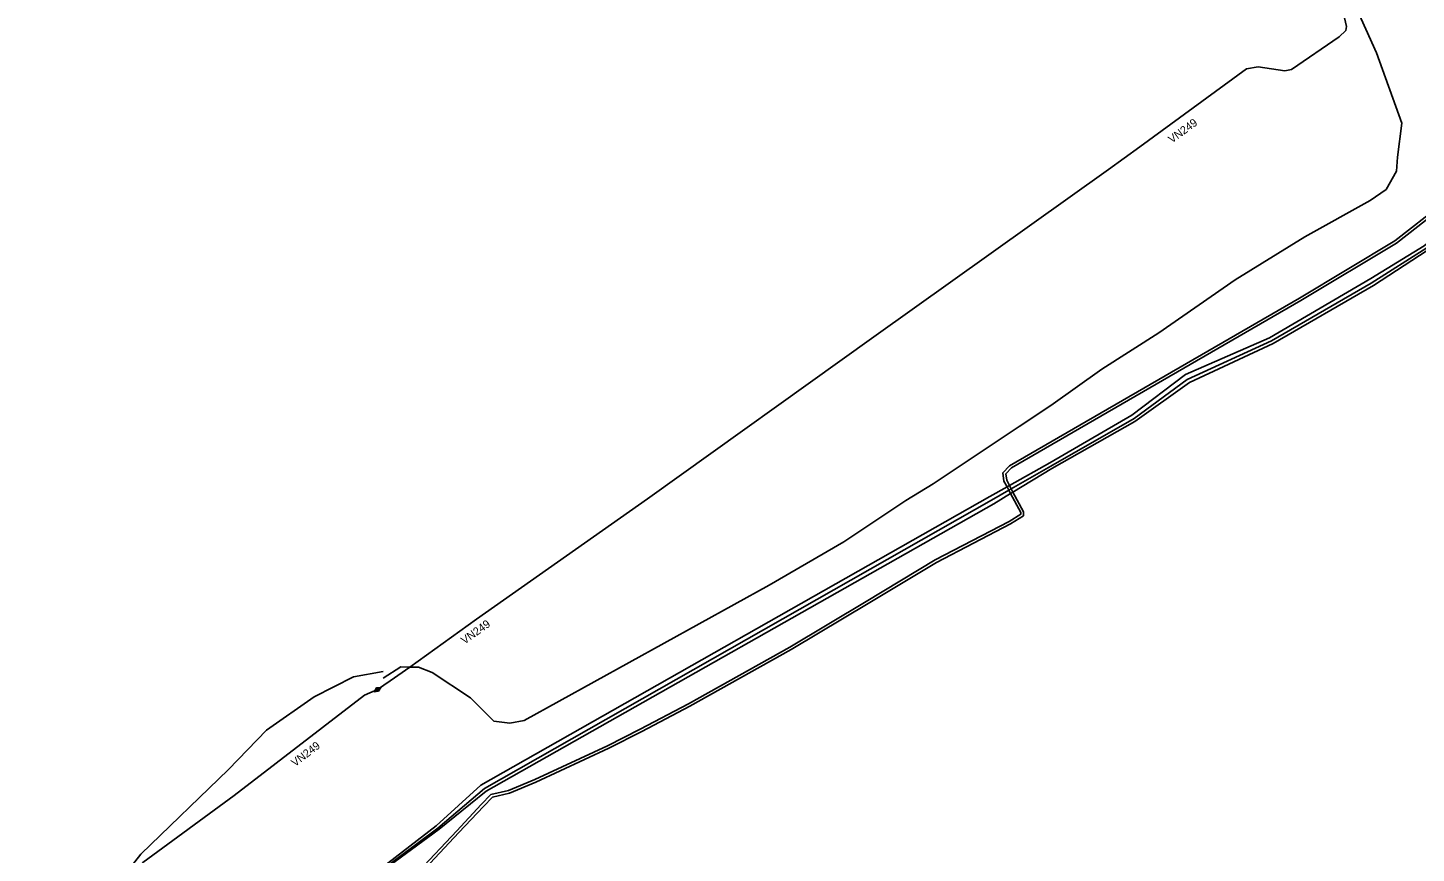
# Model space of a CAD drawing. Extents: x -643811 to -636362, y -1117362 to -1108614.
# Drawn here: x -640945.5 to -640773, y -1115905.2 to -1115802.7 of the extents above; entities that cross this region are included whole.
import ezdxf

# ---------------------------------------------------------------- set-up
doc = ezdxf.new("R2010")
doc.units = 0
for name, color, linetype in [('19', 7, 'Continuous'), ('5', 7, 'Continuous'), ('7', 7, 'Continuous'), ('9', 7, 'Continuous')]:
    doc.layers.add(name, color=color, linetype=linetype)

# ---------------------------------------------------------------- blocks, each defined once
blk = doc.blocks.new('VN870')
at = {"layer": '19'}
for points in [[(0, -0.25), (0.5, 0), (0, 0.25), (-0.5, 0), (0, -0.25)], [(0.37, 0), (0, 0.19), (-0.36, 0), (0, -0.19), (0.37, 0)], [(0.24, 0), (0, 0.12), (-0.25, 0), (0, -0.12), (0.24, 0)], [(0.12, 0), (0, 0.06), (-0.13, 0), (0, -0.06), (0.12, 0)]]:
    blk.add_lwpolyline(points, dxfattribs=at)

msp = doc.modelspace()

# ---------------------------------------------------------------- linework, layer by layer
at = {"layer": '5'}
for points in [[(-640783.38, -1115794.99), (-640782.87, -1115797), (-640782.49, -1115798.19), (-640782.33, -1115799.46), (-640781.64, -1115802.51), (-640781.73, -1115802.98), (-640782.54, -1115803.79), (-640788.49, -1115807.86), (-640789.31, -1115808), (-640792.61, -1115807.53), (-640794.06, -1115807.74), (-640807.33, -1115817.44), (-640811.23, -1115820.26), (-640840.35, -1115841.08), (-640868.48, -1115861.21), (-640889.72, -1115876.16), (-640898.02, -1115882.09), (-640900.44, -1115883.81), (-640902.03, -1115884.89)], [(-640941.02, -1115916.93), (-640938.99, -1115915.39), (-640935.56, -1115912.66), (-640933.56, -1115909.62), (-640932.69, -1115907.91), (-640931.18, -1115906.4), (-640919.83, -1115898.04), (-640903.63, -1115885.61), (-640902.03, -1115884.89)]]:
    msp.add_lwpolyline(points, dxfattribs=at)
at = {"layer": '9'}
for points in [[(-640922.22, -1115919.55), (-640914.54, -1115915.43), (-640909.61, -1115912.62), (-640902.02, -1115907.69), (-640894.52, -1115902.1), (-640888.73, -1115897.2), (-640825.74, -1115861.36), (-640823.6, -1115860.13), (-640823.29, -1115859.95), (-640818.38, -1115857.12), (-640808.01, -1115851.2), (-640801.43, -1115846.35), (-640790.97, -1115841.54), (-640778.58, -1115834.38), (-640771.68, -1115830.02), (-640765.43, -1115825.23), (-640763.48, -1115824.5), (-640760.33, -1115822), (-640747.35, -1115809.45), (-640735.75, -1115797.04), (-640722.21, -1115782.69), (-640717.76, -1115777.52), (-640710.27, -1115769.66), (-640706.07, -1115765.89)], [(-640736, -1115796.71), (-640747.8, -1115809.07), (-640760.79, -1115821.64), (-640763.73, -1115823.98), (-640765.87, -1115824.75), (-640771.99, -1115829.76), (-640778.63, -1115833.83), (-640791.21, -1115841.2), (-640801.66, -1115845.76), (-640808.3, -1115850.8), (-640818.52, -1115856.74), (-640823.52, -1115859.53), (-640823.82, -1115859.7), (-640825.97, -1115860.91), (-640889.18, -1115896.76), (-640894.76, -1115901.83), (-640902.2, -1115907.6), (-640909.81, -1115912.38), (-640914.84, -1115915.34), (-640922.83, -1115919.43)], [(-640781.91, -1115796.89), (-640777.92, -1115805.79), (-640774.77, -1115814.53), (-640775.32, -1115818.72), (-640775.45, -1115820.49), (-640776.73, -1115822.74), (-640778.71, -1115824.12), (-640786.81, -1115828.63), (-640795.49, -1115833.97), (-640804.94, -1115840.57), (-640812.06, -1115845.1), (-640818.36, -1115849.58), (-640822.31, -1115852.22), (-640833.01, -1115859.34), (-640836.4, -1115861.39), (-640844.1, -1115866.55), (-640853.38, -1115871.91), (-640883.79, -1115888.74), (-640885.58, -1115889.05), (-640887.58, -1115888.81), (-640890.48, -1115885.91), (-640895.24, -1115882.79), (-640896.93, -1115882.09), (-640898.02, -1115882.09), (-640899.11, -1115882.08), (-640901.31, -1115883.48)], [(-640896.93, -1115907.51), (-640892.17, -1115902.43), (-640889.13, -1115899.18), (-640887.93, -1115897.95), (-640885.74, -1115897.43), (-640882.48, -1115896.07), (-640873.45, -1115891.87), (-640869.39, -1115889.8), (-640863.38, -1115886.65), (-640850.8, -1115879.62), (-640841.33, -1115873.95), (-640832.74, -1115868.79), (-640823.55, -1115863.99), (-640822.11, -1115863.11), (-640822.12, -1115862.9), (-640823.38, -1115860.54), (-640823.6, -1115860.13), (-640823.82, -1115859.7), (-640824.2, -1115859), (-640824.34, -1115857.97), (-640823.5, -1115857.08), (-640787.49, -1115836.26), (-640775.65, -1115829.12), (-640746.45, -1115806.34)], [(-640896.67, -1115907.75), (-640891.92, -1115902.67), (-640888.87, -1115899.42), (-640887.75, -1115898.27), (-640885.63, -1115897.76), (-640882.34, -1115896.39), (-640873.3, -1115892.19), (-640869.19, -1115890.09), (-640863.23, -1115886.97), (-640850.62, -1115879.92), (-640840.85, -1115874.07), (-640832.56, -1115869.09), (-640823.38, -1115864.3), (-640821.76, -1115863.3), (-640821.77, -1115862.81), (-640823.08, -1115860.35), (-640823.29, -1115859.95), (-640823.52, -1115859.53), (-640823.86, -1115858.89), (-640823.97, -1115858.09), (-640823.28, -1115857.36), (-640787.31, -1115836.56), (-640775.45, -1115829.41), (-640746.22, -1115806.6)], [(-640921, -1115920.28), (-640919.33, -1115918.44), (-640914.2, -1115915.56), (-640909.45, -1115912.8), (-640901.86, -1115907.73), (-640894.35, -1115902.22), (-640888.51, -1115897.51), (-640825.44, -1115861.8), (-640823.38, -1115860.54), (-640823.08, -1115860.35), (-640818.26, -1115857.41), (-640807.92, -1115851.6), (-640801.15, -1115846.73), (-640790.76, -1115841.88), (-640778.27, -1115834.7), (-640771.61, -1115830.33)], [(-640901.31, -1115882.65), (-640905.02, -1115883.3), (-640909.91, -1115885.81), (-640915.84, -1115889.94), (-640920.55, -1115894.82), (-640931.42, -1115905.36), (-640935.75, -1115910.86), (-640939.97, -1115914.86), (-640942.55, -1115918.4), (-640944.67, -1115921.22), (-640945.48, -1115923.07), (-640945.48, -1115925.3), (-640945, -1115927.41), (-640943.63, -1115929.13), (-640940.32, -1115929.52), (-640937.76, -1115927.79)]]:
    msp.add_lwpolyline(points, dxfattribs=at)

# ---------------------------------------------------------------- block references
at = {"layer": '19', "rotation": 32.99999999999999}
msp.add_blockref('VN870', (-640902.03, -1115884.89), dxfattribs=at)

# ---------------------------------------------------------------- texts
at = {"layer": '7'}
for rotation, p in [(36.1658, (-640803.34, -1115817.06)), (35.5124, (-640891.22, -1115879.32)), (37.4984, (-640912.28, -1115894.53))]:
    msp.add_text('VN249', height=0.994, rotation=rotation, dxfattribs=at).set_placement(p)

doc.saveas('drawing.dxf')
